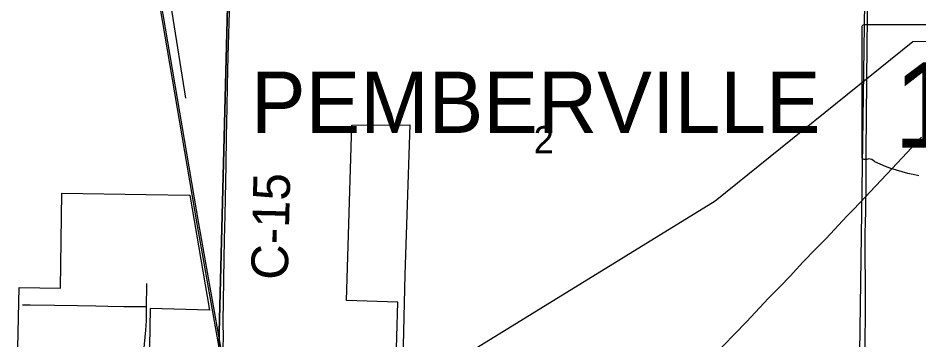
# Model space of a CAD drawing. Extents: x 0 to 34, y 0 to 22.
# Drawn here: x 4.781 to 6.172, y 17.701 to 18.197 of the extents above; entities that cross this region are included whole.
import ezdxf

# ---------------------------------------------------------------- set-up
doc = ezdxf.new("R2010")
doc.units = 0
for name, color, linetype in [('GM_X_City_Street', 7, 'Continuous'), ('GM_X_Corporation', 7, 'Continuous'), ('GM_X_Corporation_Text', 7, 'Continuous'), ('GM_X_County_Road', 7, 'Continuous'), ('GM_X_County_Road_Text', 7, 'Continuous'), ('GM_X_Minor_River', 7, 'Continuous'), ('GM_X_Rail_Line', 7, 'Continuous'), ('GM_X_Section', 7, 'Continuous'), ('GM_X_Section_Text', 7, 'Continuous'), ('GM_X_State_Route', 7, 'Continuous'), ('GM_X_State_Shield', 7, 'Continuous'), ('GM_X_Township_Road', 7, 'Continuous')]:
    doc.layers.add(name, color=color, linetype=linetype)

msp = doc.modelspace()

# ---------------------------------------------------------------- linework, layer by layer
at = {"layer": 'GM_X_City_Street'}
for points in [[(4.9756, 17.6836), (4.9787, 17.716), (4.9796, 17.7301), (4.9795, 17.7394), (4.9797, 17.7523), (4.98, 17.7659), (4.9801, 17.7722), (4.9803, 17.788)], [(4.7885, 17.7549), (4.8002, 17.7551), (4.8376, 17.7545), (4.8734, 17.754), (4.9014, 17.7534), (4.9201, 17.7531), (4.945, 17.7526), (4.9746, 17.7523), (4.9797, 17.7523)]]:
    msp.add_lwpolyline(points, dxfattribs=at)
at = {"layer": 'GM_X_Corporation'}
for points in [[(5.3649, 17.6521), (5.3679, 17.7589), (5.2883, 17.7616), (5.2966, 18.0323), (5.3864, 18.0325), (5.3787, 17.8017), (5.3744, 17.6259)], [(4.7813, 17.6888), (4.7833, 17.7815), (4.8471, 17.7809), (4.8489, 17.9271), (4.9794, 17.9253), (5.0467, 17.9241), (5.0772, 17.7467), (4.9854, 17.7495), (4.9837, 17.6616)]]:
    msp.add_lwpolyline(points, dxfattribs=at)
at = {"layer": 'GM_X_County_Road'}
msp.add_lwpolyline([(5.0933, 17.6587), (5.0933, 17.6621), (5.0936, 17.6658), (5.0953, 17.6733), (5.0975, 17.6849), (5.0979, 17.6895), (5.0983, 17.6937), (5.0985, 17.7), (5.0982, 17.7326), (5.0986, 17.7575), (5.099, 17.7949), (5.1002, 17.8555), (5.101, 17.8928), (5.1015, 17.9193), (5.1027, 17.9706), (5.1032, 18.0142), (5.1043, 18.0592), (5.1049, 18.0935), (5.106, 18.1386), (5.1082, 18.2237)], dxfattribs=at)
at = {"layer": 'GM_X_Minor_River'}
msp.add_lwpolyline([(4.9794, 18.4275), (4.999, 18.3217), (5.0188, 18.2062), (5.0402, 18.074)], dxfattribs=at)
at = {"layer": 'GM_X_Rail_Line'}
for points in [[(5.1845, 16.9583), (5.1759, 17.0275), (5.1512, 17.2319), (5.1278, 17.4186), (5.1173, 17.5021), (5.1014, 17.6375), (5.0581, 17.8798), (4.9514, 18.5044), (4.7757, 19.5202), (4.6462, 20.2762), (4.5385, 20.9)], [(5.533, 14.1), (5.4414, 14.8452), (5.2368, 16.5291), (5.1973, 16.873), (5.1794, 17.0253), (5.1537, 17.2322), (5.1303, 17.4189), (5.1198, 17.5024), (5.1038, 17.6379), (5.0605, 17.8802), (4.9539, 18.5048), (4.7781, 19.5207), (4.6486, 20.2766), (4.541, 20.9)], [(5.1236, 17.5022), (5.2885, 17.5882), (5.4372, 17.6568), (5.858, 17.9153), (6.1629, 18.1611), (6.3042, 18.1643), (6.4687, 18.2265), (7.1295, 18.535)]]:
    msp.add_lwpolyline(points, dxfattribs=at)
at = {"layer": 'GM_X_Section'}
for points in [[(4.1339, 18.5191), (5.1123, 18.5161), (5.0874, 17.5326), (4.6502, 17.5462), (4.0852, 17.5486), (4.1085, 18.519)], [(5.1313, 18.516), (6.0923, 18.5098), (6.0785, 17.5378), (5.0874, 17.5326), (5.1123, 18.5161)]]:
    msp.add_lwpolyline(points, close=True, dxfattribs=at)
at = {"layer": 'GM_X_State_Route'}
msp.add_lwpolyline([(5.8596, 17.6809), (5.8714, 17.693), (5.8873, 17.7092), (5.9067, 17.7294), (5.9398, 17.7645), (5.9582, 17.7835), (5.9734, 17.799), (5.9934, 17.8207), (6.0129, 17.8408), (6.0292, 17.8575), (6.0611, 17.8915), (6.0709, 17.9015), (6.0907, 17.9225), (6.0972, 17.9294), (6.1309, 17.9652), (6.1765, 18.0137)], dxfattribs=at)
at = {"layer": 'GM_X_State_Shield'}
for p, q in [((6.0842, 18.1832), (6.0842, 17.9831)), ((6.1839, 18.1867), (6.0874, 18.1867))]:
    msp.add_line(p, q, dxfattribs=at)
for centre, major_axis, start_param, end_param in [((6.0879, 18.1837), (0.00382, 0), 1.712693, 3.28349), ((6.088, 17.9827), (0.00385, 0), 3.00124, 4.508301), ((6.0886, 18.0032), (0.0294, 0), 4.665946, 4.897461), ((6.0946, 17.9716), (0.0106, 0), 0.519207, 1.627899), ((6.2284, 18.1514), (0.2524, 0), 4.195997, 4.488961)]:
    msp.add_ellipse(centre, major_axis=major_axis, ratio=0.8, start_param=start_param, end_param=end_param, dxfattribs=at)
at = {"layer": 'GM_X_Township_Road'}
for points in [[(6.0907, 17.9225), (6.0911, 17.9364), (6.0911, 17.9581), (6.0911, 17.9908), (6.0914, 18.0452), (6.092, 18.1011), (6.0926, 18.154), (6.0935, 18.241), (6.0943, 18.3141), (6.0954, 18.3996), (6.0959, 18.426), (6.0963, 18.4508), (6.0968, 18.4757), (6.0976, 18.4944), (6.0978, 18.4997)], [(6.0873, 17.4152), (6.0875, 17.4375), (6.0876, 17.467), (6.0875, 17.495), (6.088, 17.5836), (6.0885, 17.6349), (6.0892, 17.6831), (6.0897, 17.7561), (6.0897, 17.7903), (6.0896, 17.8292), (6.0896, 17.8649), (6.0902, 17.8991), (6.0906, 17.9193), (6.0907, 17.9225)]]:
    msp.add_lwpolyline(points, dxfattribs=at)

# ---------------------------------------------------------------- texts
at = {"layer": 'GM_X_Corporation_Text'}
msp.add_text('PEMBERVILLE', height=0.094697, rotation=0, dxfattribs=at).set_placement((5.1409, 18.0201))
at = {"layer": 'GM_X_County_Road_Text'}
msp.add_text('C-15', height=0.05682, rotation=88.6573, dxfattribs=at).set_placement((5.1979, 17.793))
at = {"layer": 'GM_X_Section_Text'}
msp.add_text('2', height=0.0419, rotation=0, dxfattribs=at).set_placement((5.5776, 17.9887))
at = {"layer": 'GM_X_State_Shield'}
msp.add_text('105', height=0.13184, dxfattribs=at).set_placement((6.1333, 17.9972))

doc.saveas('drawing.dxf')
